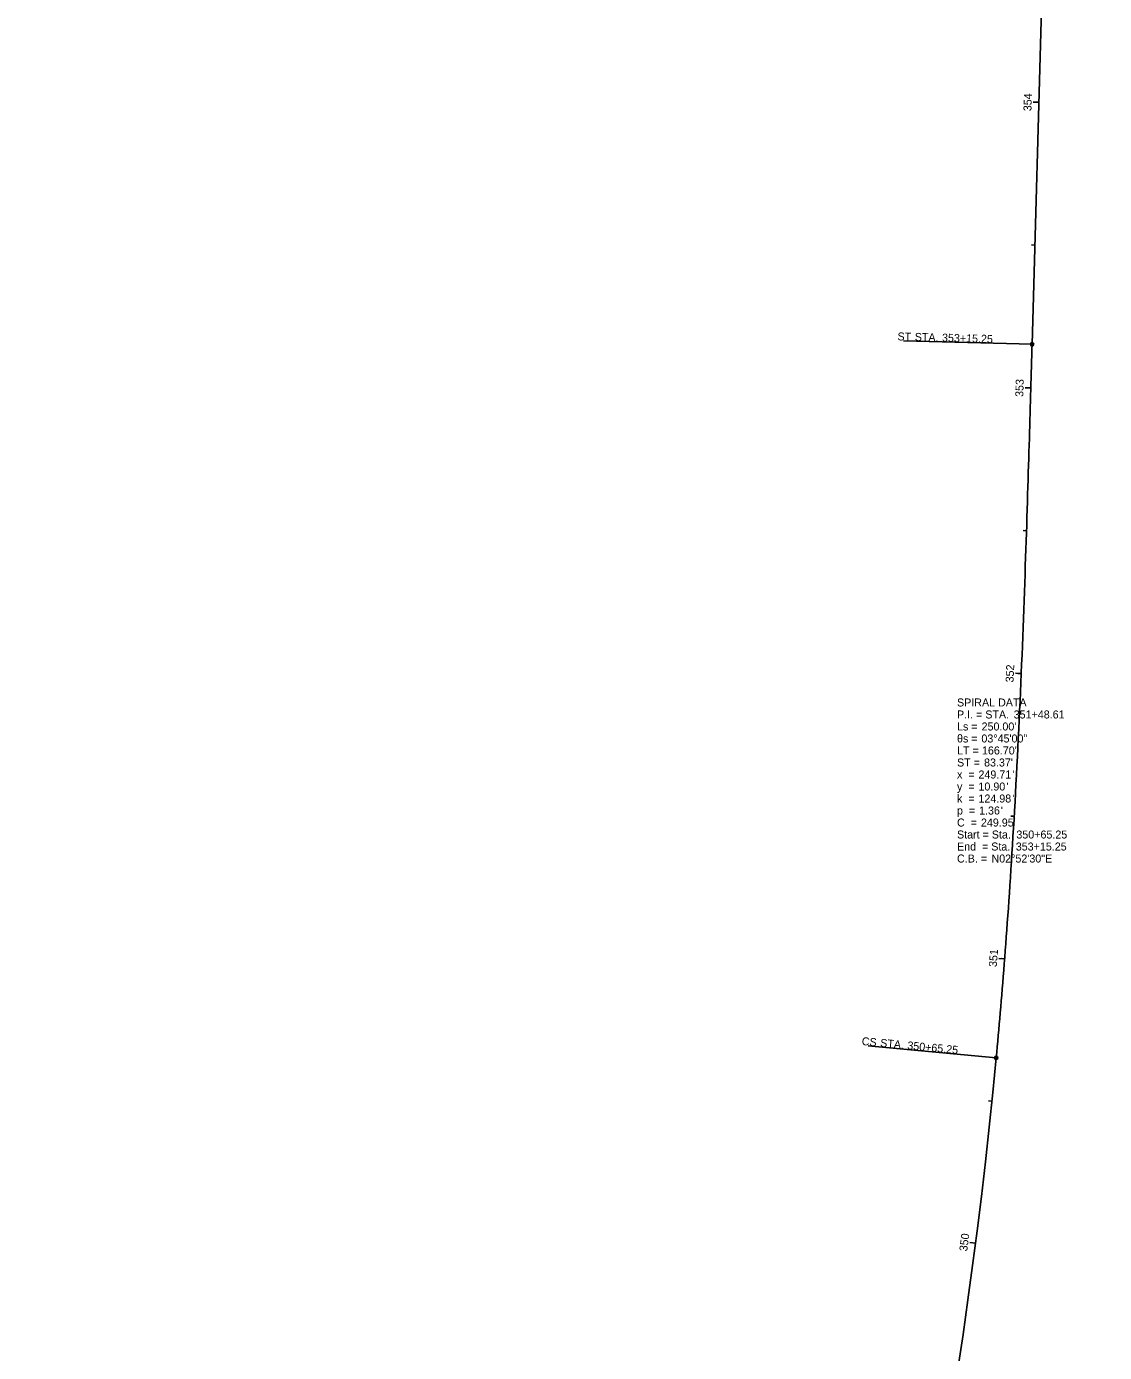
# Model space of a CAD drawing. Extents: x 1380776 to 1381901, y 503546 to 507267.
# Drawn here: x 1381410.1 to 1381787.2, y 504927.1 to 505391.1 of the extents above; entities that cross this region are included whole.
import ezdxf

# ---------------------------------------------------------------- set-up
doc = ezdxf.new("R2010")
doc.units = 0
for name, color, linetype in [('_CIVIL_CONSTRUCTION', 7, 'Continuous'), ('DR_P_Storm_Sewer', 7, 'Continuous'), ('DR_X_Cells', 7, 'Continuous'), ('DR_X_Storm_Sewer', 7, 'Continuous'), ('GK_Drainage_Nodes', 7, 'Continuous'), ('SC_Scratch1', 7, 'Continuous'), ('SC_Scratch3', 7, 'Continuous')]:
    doc.layers.add(name, color=color, linetype=linetype)

msp = doc.modelspace()

# ---------------------------------------------------------------- linework, layer by layer
at = {"layer": '_CIVIL_CONSTRUCTION'}
for p, q in [((1381764.27, 505364.6), (1381763.07, 505364.64)), ((1381761.87, 505279.88), (1381716.89, 505281.16)), ((1381761.43, 505264.65), (1381760.24, 505264.69)), ((1381758.07, 505164.71), (1381756.87, 505164.76)), ((1381752.29, 505064.88), (1381751.09, 505064.97)), ((1381749.33, 505030.25), (1381704.53, 505034.47)), ((1381742.11, 504965.41), (1381740.13, 504965.67))]:
    msp.add_line(p, q, dxfattribs=at)
for centre in [(1381761.87, 505279.88), (1381749.33, 505030.25)]:
    msp.add_circle(centre, 0.6, dxfattribs=at)
at = {"layer": 'DR_P_Storm_Sewer'}
for p, q in [((1381761.87, 505279.88), (1381716.89, 505281.16)), ((1381749.33, 505030.25), (1381704.53, 505034.47)), ((1381742.11, 504965.41), (1381740.13, 504965.67))]:
    msp.add_line(p, q, dxfattribs=at)
for centre in [(1381761.87, 505279.88), (1381749.33, 505030.25)]:
    msp.add_circle(centre, 0.6, dxfattribs=at)
at = {"layer": 'DR_X_Storm_Sewer'}
for p, q in [((1381764.27, 505364.6), (1381762.27, 505364.66)), ((1381762.85, 505314.62), (1381761.65, 505314.66)), ((1381761.87, 505279.88), (1381716.89, 505281.16)), ((1381761.43, 505264.65), (1381759.44, 505264.71)), ((1381759.92, 505214.67), (1381758.72, 505214.71)), ((1381758.07, 505164.71), (1381756.07, 505164.79)), ((1381755.61, 505114.77), (1381754.41, 505114.84)), ((1381752.29, 505064.88), (1381750.29, 505065.04)), ((1381749.33, 505030.25), (1381704.53, 505034.47)), ((1381747.84, 505015.08), (1381746.65, 505015.2)), ((1381742.11, 504965.41), (1381740.13, 504965.67))]:
    msp.add_line(p, q, dxfattribs=at)
for centre in [(1381761.87, 505279.88), (1381749.33, 505030.25)]:
    msp.add_circle(centre, 0.6, dxfattribs=at)
at = {"layer": 'SC_Scratch1'}
msp.add_line((1381761.87, 505279.88), (1381787.2, 506172.79), dxfattribs=at)
msp.add_arc((1379847.87, 505209.16), 1909.86, 308.35888, 354.62505, dxfattribs=at)
msp.add_arc((1379847.87, 505209.16), 1909.86, 308.35888, 354.62505, dxfattribs=at)
msp.add_open_spline([(1381749.33, 505030.25), (1381750.31, 505040.62), (1381752.09, 505061.38), (1381755.06, 505102.94), (1381757.81, 505154.96), (1381759.72, 505207.01), (1381760.98, 505248.65), (1381761.57, 505269.48), (1381761.87, 505279.89)], degree=3, dxfattribs=at)
msp.add_open_spline([(1381749.33, 505030.25), (1381750.31, 505040.62), (1381752.09, 505061.38), (1381755.06, 505102.94), (1381757.81, 505154.96), (1381759.72, 505207.01), (1381760.98, 505248.65), (1381761.57, 505269.48), (1381761.87, 505279.89)], degree=3, dxfattribs=at)

# ---------------------------------------------------------------- texts
at = {"layer": '_CIVIL_CONSTRUCTION'}
for s, rotation, p in [('ST', 358.375, (1381714.77, 505281.27)), (' STA. ', 358.375, (1381719.77, 505281.13)), ('353+15.25', 358.375, (1381730.34, 505280.83)), ('CS', 354.625, (1381702.21, 505034.73)), (' STA. ', 354.625, (1381707.62, 505034.23)), ('350+65.25', 354.625, (1381718.15, 505033.23)), ('350', 82.6677, (1381739.16, 504962.42))]:
    msp.add_text(s, height=2.8, rotation=rotation, dxfattribs=at).set_placement(p)
at = {"layer": 'DR_P_Storm_Sewer'}
for s, rotation, p in [('ST', 358.375, (1381714.77, 505281.27)), (' STA. ', 358.375, (1381719.77, 505281.13)), ('353+15.25', 358.375, (1381730.34, 505280.83)), ('CS', 354.625, (1381702.21, 505034.73)), (' STA. ', 354.625, (1381707.62, 505034.23)), ('350+65.25', 354.625, (1381718.15, 505033.23)), ('350', 82.6677, (1381739.16, 504962.42))]:
    msp.add_text(s, height=2.8, rotation=rotation, dxfattribs=at).set_placement(p)
at = {"layer": 'DR_X_Cells'}
for s, p in [('SPIRAL DATA', (1381735.62, 505153.17)), ('P.I. = STA. ', (1381735.62, 505148.97)), ('351+48.61', (1381755.44, 505148.97)), ('Ls = ', (1381735.62, 505144.77)), ("250.00'", (1381744.21, 505144.77)), ('θs = ', (1381735.62, 505140.57)), ('03°45\'00"', (1381744.15, 505140.57)), ('LT = ', (1381735.62, 505136.37)), ("166.70'", (1381744.35, 505136.37)), ('ST = ', (1381735.62, 505132.17)), ("83.37'", (1381745.08, 505132.17)), ('x  = ', (1381735.62, 505127.97)), ('249.71', (1381743.12, 505127.97)), ("'", (1381755.08, 505127.97)), ('y  = ', (1381735.62, 505123.77)), ('10.90', (1381743.12, 505123.77)), ("'", (1381752.9, 505123.77)), ('k  = ', (1381735.62, 505119.57)), ('124.98', (1381743.12, 505119.57)), ("'", (1381755.08, 505119.57)), ('p  = ', (1381735.62, 505115.37)), ('1.36', (1381743.34, 505115.37)), ("'", (1381750.95, 505115.37)), ('C  = ', (1381735.62, 505111.17)), ("249.95'", (1381743.99, 505111.17)), ('Start = Sta. ', (1381735.62, 505106.97)), ('End  = Sta. ', (1381735.62, 505102.77)), ('353+15.25', (1381756.17, 505102.77)), ('350+65.25', (1381756.38, 505106.97)), ('C.B. = ', (1381735.62, 505098.57)), ('N02°52\'30"E', (1381747.68, 505098.57))]:
    msp.add_text(s, height=2.8, dxfattribs=at).set_placement(p)
at = {"layer": 'DR_X_Storm_Sewer'}
for s, rotation, p in [('354', 88.375, (1381761.64, 505361.41)), ('ST', 358.375, (1381714.77, 505281.27)), (' STA. ', 358.375, (1381719.77, 505281.13)), ('353+15.25', 358.375, (1381730.34, 505280.83)), ('353', 88.3611, (1381758.8, 505261.45)), ('352', 87.5781, (1381755.39, 505161.54)), ('351', 85.5952, (1381749.51, 505061.94)), ('CS', 354.625, (1381702.21, 505034.73)), (' STA. ', 354.625, (1381707.62, 505034.23)), ('350+65.25', 354.625, (1381718.15, 505033.23)), ('350', 82.6677, (1381739.16, 504962.42))]:
    msp.add_text(s, height=2.8, rotation=rotation, dxfattribs=at).set_placement(p)
at = {"layer": 'GK_Drainage_Nodes'}
for s, p in [('SPIRAL DATA', (1381735.62, 505153.17)), ('P.I. = STA. ', (1381735.62, 505148.97)), ('351+48.61', (1381755.44, 505148.97)), ('Ls = ', (1381735.62, 505144.77)), ("250.00'", (1381744.21, 505144.77)), ('θs = ', (1381735.62, 505140.57)), ('03°45\'00"', (1381744.15, 505140.57)), ('LT = ', (1381735.62, 505136.37)), ("166.70'", (1381744.35, 505136.37)), ('ST = ', (1381735.62, 505132.17)), ("83.37'", (1381745.08, 505132.17)), ('x  = ', (1381735.62, 505127.97)), ('249.71', (1381743.12, 505127.97)), ("'", (1381755.08, 505127.97)), ('y  = ', (1381735.62, 505123.77)), ('10.90', (1381743.12, 505123.77)), ("'", (1381752.9, 505123.77)), ('k  = ', (1381735.62, 505119.57)), ('124.98', (1381743.12, 505119.57)), ("'", (1381755.08, 505119.57)), ('p  = ', (1381735.62, 505115.37)), ('1.36', (1381743.34, 505115.37)), ("'", (1381750.95, 505115.37)), ('C  = ', (1381735.62, 505111.17)), ("249.95'", (1381743.99, 505111.17)), ('Start = Sta. ', (1381735.62, 505106.97)), ('End  = Sta. ', (1381735.62, 505102.77)), ('353+15.25', (1381756.17, 505102.77)), ('350+65.25', (1381756.38, 505106.97)), ('C.B. = ', (1381735.62, 505098.57)), ('N02°52\'30"E', (1381747.68, 505098.57))]:
    msp.add_text(s, height=2.8, dxfattribs=at).set_placement(p)
at = {"layer": 'SC_Scratch3'}
for s, p in [('SPIRAL DATA', (1381735.62, 505153.17)), ('P.I. = STA. ', (1381735.62, 505148.97)), ('351+48.61', (1381755.44, 505148.97)), ('Ls = ', (1381735.62, 505144.77)), ("250.00'", (1381744.21, 505144.77)), ('θs = ', (1381735.62, 505140.57)), ('03°45\'00"', (1381744.15, 505140.57)), ('LT = ', (1381735.62, 505136.37)), ("166.70'", (1381744.35, 505136.37)), ('ST = ', (1381735.62, 505132.17)), ("83.37'", (1381745.08, 505132.17)), ('x  = ', (1381735.62, 505127.97)), ('249.71', (1381743.12, 505127.97)), ("'", (1381755.08, 505127.97)), ('y  = ', (1381735.62, 505123.77)), ('10.90', (1381743.12, 505123.77)), ("'", (1381752.9, 505123.77)), ('k  = ', (1381735.62, 505119.57)), ('124.98', (1381743.12, 505119.57)), ("'", (1381755.08, 505119.57)), ('p  = ', (1381735.62, 505115.37)), ('1.36', (1381743.34, 505115.37)), ("'", (1381750.95, 505115.37)), ('C  = ', (1381735.62, 505111.17)), ("249.95'", (1381743.99, 505111.17)), ('Start = Sta. ', (1381735.62, 505106.97)), ('End  = Sta. ', (1381735.62, 505102.77)), ('353+15.25', (1381756.17, 505102.77)), ('350+65.25', (1381756.38, 505106.97)), ('C.B. = ', (1381735.62, 505098.57)), ('N02°52\'30"E', (1381747.68, 505098.57))]:
    msp.add_text(s, height=2.8, dxfattribs=at).set_placement(p)

doc.saveas('drawing.dxf')
